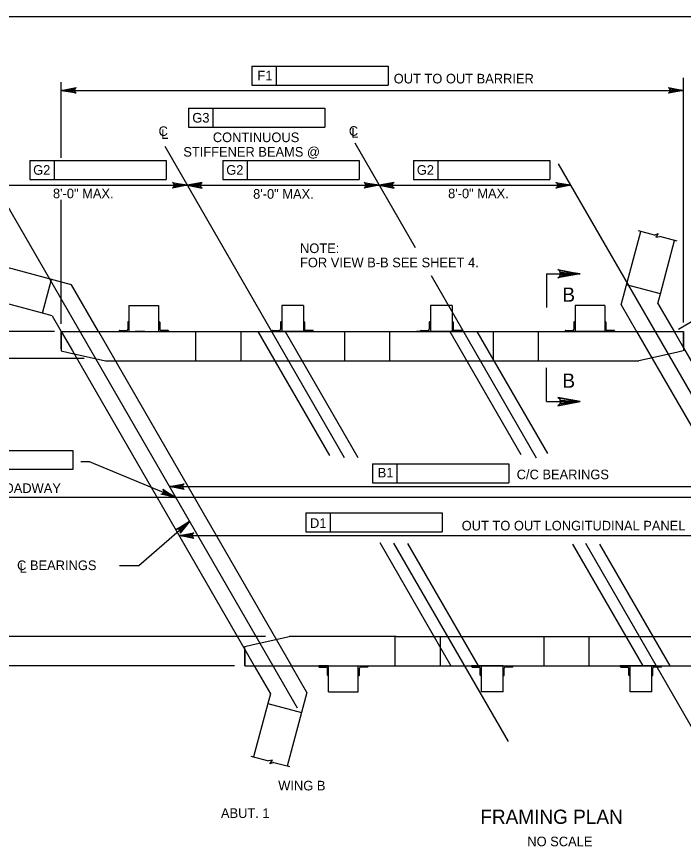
# Model space of a CAD drawing. Extents: x 638268 to 640277, y 295465 to 298435.
# Drawn here: x 639421 to 639628.9, y 296973.8 to 297232.5 of the extents above; entities that cross this region are included whole.
import ezdxf

# ---------------------------------------------------------------- set-up
doc = ezdxf.new("R2010")
doc.units = 0
for name, color, linetype in [('2', 7, 'Continuous'), ('3', 7, 'Continuous'), ('4', 7, 'Continuous')]:
    doc.layers.add(name, color=color, linetype=linetype)

msp = doc.modelspace()

# ---------------------------------------------------------------- linework, layer by layer
at = {"layer": '2'}
for p, q in [((639316.46, 297232.46), (640102.46, 297232.46)), ((639609.49, 297142.63), (639615.62, 297165.51)), ((639621.7, 297146.01), (639626.16, 297162.69)), ((639438.09, 297148.88), (639415.21, 297155.01)), ((639586.2, 297152.3), (639586.2, 297141.81)), ((639586.2, 297152.3), (639596.69, 297152.3)), ((639429.07, 297140), (639431.89, 297150.55)), ((639446.52, 297134.29), (639438.09, 297148.88)), ((639621.7, 297146.01), (639611.15, 297148.83)), ((639429.07, 297140), (639412.39, 297144.47)), ((639620.9, 297143.05), (639621.7, 297146.01)), ((639455.99, 297142.38), (639465.22, 297142.38)), ((639455.99, 297142.38), (639455.99, 297134.29)), ((639465.22, 297142.38), (639465.22, 297134.29)), ((639510.38, 297142.38), (639503.65, 297142.38)), ((639510.38, 297142.38), (639503.65, 297142.38)), ((639503.65, 297142.38), (639503.65, 297134.29)), ((639510.38, 297142.38), (639510.38, 297134.29)), ((639556.74, 297142.38), (639550.02, 297142.38)), ((639556.74, 297142.38), (639550.02, 297142.38)), ((639556.74, 297142.38), (639550.02, 297142.38)), ((639550.02, 297142.38), (639550.02, 297134.29)), ((639556.74, 297142.38), (639556.74, 297134.29)), ((639604.36, 297142.38), (639595.12, 297142.38)), ((639595.12, 297142.38), (639595.12, 297134.29)), ((639604.36, 297142.38), (639604.36, 297134.29)), ((639609.49, 297142.63), (639614.31, 297134.29)), ((639620.9, 297143.05), (639625.96, 297134.29)), ((639432.02, 297139.21), (639429.07, 297140)), ((639432.02, 297139.21), (639434.87, 297134.29)), ((639455.62, 297137.2), (639455.62, 297135.01)), ((639455.81, 297137.38), (639455.99, 297137.38)), ((639455.99, 297137.38), (639455.99, 297134.29)), ((639465.41, 297137.38), (639465.22, 297137.38)), ((639465.22, 297137.38), (639465.22, 297134.29)), ((639465.59, 297137.2), (639465.59, 297135.01)), ((639503.29, 297137.2), (639503.29, 297135.01)), ((639503.47, 297137.38), (639503.65, 297137.38)), ((639503.65, 297137.38), (639503.65, 297134.29)), ((639510.56, 297137.38), (639510.38, 297137.38)), ((639510.38, 297137.38), (639510.38, 297134.29)), ((639510.74, 297137.2), (639510.74, 297135.01)), ((639549.65, 297137.2), (639549.65, 297135.01)), ((639549.83, 297137.38), (639550.02, 297137.38)), ((639550.02, 297137.38), (639550.02, 297134.29)), ((639556.92, 297137.38), (639556.74, 297137.38)), ((639556.74, 297137.38), (639556.74, 297134.29)), ((639557.11, 297137.2), (639557.11, 297135.01)), ((639594.76, 297137.2), (639594.76, 297135.01)), ((639594.94, 297137.38), (639595.12, 297137.38)), ((639595.12, 297137.38), (639595.12, 297134.29)), ((639604.54, 297137.38), (639604.36, 297137.38)), ((639604.36, 297137.38), (639604.36, 297134.29)), ((639604.72, 297137.2), (639604.72, 297135.01)), ((639434.87, 297134.29), (639628.88, 297134.29)), ((639434.87, 297134.29), (639438.37, 297128.22)), ((639434.87, 297134.29), (639628.88, 297134.29)), ((639434.87, 297134.29), (639434.87, 297128.26)), ((639434.87, 297128.9), (639434.87, 297134.29)), ((639446.52, 297134.29), (639506.69, 297030.06)), ((639452.9, 297134.47), (639452.9, 297134.29)), ((639453.08, 297134.65), (639455.26, 297134.65)), ((639455.99, 297134.29), (639465.22, 297134.29)), ((639460.99, 297134.29), (639457.9, 297134.29)), ((639465.22, 297134.29), (639468.32, 297134.29)), ((639468.13, 297134.65), (639465.95, 297134.65)), ((639468.32, 297134.47), (639468.32, 297134.29)), ((639476.78, 297134.29), (639476.78, 297125.17)), ((639490.85, 297134.29), (639490.85, 297125.17)), ((639500.56, 297134.47), (639500.56, 297134.29)), ((639503.65, 297134.29), (639500.56, 297134.29)), ((639500.74, 297134.65), (639502.92, 297134.65)), ((639511.63, 297134.29), (639502.4, 297134.29)), ((639510.38, 297134.29), (639503.65, 297134.29)), ((639510.38, 297134.29), (639513.47, 297134.29)), ((639513.29, 297134.65), (639511.11, 297134.65)), ((639513.47, 297134.47), (639513.47, 297134.29)), ((639523.18, 297134.29), (639523.19, 297125.17)), ((639537.21, 297134.29), (639537.21, 297125.17)), ((639548.76, 297134.29), (639545.67, 297134.29)), ((639546.92, 297134.47), (639546.92, 297134.29)), ((639550.02, 297134.29), (639546.92, 297134.29)), ((639547.11, 297134.65), (639549.29, 297134.65)), ((639558, 297134.29), (639548.76, 297134.29)), ((639558, 297134.29), (639548.76, 297134.29)), ((639556.74, 297134.29), (639550.02, 297134.29)), ((639556.74, 297134.29), (639559.83, 297134.29)), ((639559.65, 297134.65), (639557.47, 297134.65)), ((639558, 297134.29), (639561.09, 297134.29)), ((639559.83, 297134.47), (639559.83, 297134.29)), ((639569.55, 297134.29), (639569.55, 297125.17)), ((639583.57, 297134.29), (639583.57, 297125.17)), ((639592.03, 297134.47), (639592.03, 297134.29)), ((639595.12, 297134.29), (639592.03, 297134.29)), ((639592.21, 297134.65), (639594.4, 297134.65)), ((639604.36, 297134.29), (639595.12, 297134.29)), ((639604.36, 297134.29), (639607.45, 297134.29)), ((639607.27, 297134.65), (639605.09, 297134.65)), ((639607.45, 297134.47), (639607.45, 297134.29)), ((639614.31, 297134.29), (639674.49, 297030.06)), ((639625.96, 297134.29), (639628.88, 297129.24)), ((639628.88, 297129.24), (639628.88, 297134.29)), ((639628.88, 297134.29), (639628.88, 297128.26)), ((639628.88, 297129.24), (639682.63, 297036.13)), ((639434.87, 297128.26), (639437.04, 297127.77)), ((639437.04, 297127.77), (639448.71, 297125.17)), ((639438.37, 297128.22), (639492.13, 297035.11)), ((639626.69, 297127.77), (639615.01, 297125.17)), ((639628.86, 297128.26), (639626.69, 297127.77)), ((639448.71, 297125.17), (639615.01, 297125.17)), ((639586.2, 297112.45), (639586.2, 297122.94)), ((639586.2, 297112.45), (639596.69, 297112.45)), ((639494.3, 297036.58), (639505.98, 297039.18)), ((639539.28, 297039.18), (639505.98, 297039.18)), ((639539.04, 297030.06), (639539.04, 297039.18)), ((639539.28, 297039.18), (639674.46, 297039.18)), ((639553.11, 297030.06), (639553.11, 297039.18)), ((639585.45, 297030.06), (639585.45, 297039.18)), ((639599.47, 297030.06), (639599.47, 297039.18)), ((639492.13, 297036.09), (639494.3, 297036.58)), ((639492.13, 297030.06), (639492.13, 297036.09)), ((639492.13, 297035.23), (639492.13, 297030.06)), ((639492.13, 297035.11), (639495.04, 297030.06)), ((639492.13, 297030.06), (639686.14, 297030.06)), ((639492.13, 297030.06), (639686.14, 297030.06)), ((639495.04, 297030.06), (639500.1, 297021.3)), ((639511.51, 297021.72), (639506.69, 297030.06)), ((639515.16, 297029.88), (639515.16, 297030.06)), ((639518.25, 297030.06), (639515.16, 297030.06)), ((639515.34, 297029.7), (639517.52, 297029.7)), ((639517.88, 297027.15), (639517.88, 297029.33)), ((639518.25, 297030.06), (639527.49, 297030.06)), ((639518.25, 297026.97), (639518.25, 297030.06)), ((639518.25, 297021.97), (639518.25, 297030.06)), ((639527.49, 297030.06), (639530.58, 297030.06)), ((639527.49, 297026.97), (639527.49, 297030.06)), ((639527.49, 297021.97), (639527.49, 297030.06)), ((639527.85, 297027.15), (639527.85, 297029.33)), ((639530.39, 297029.7), (639528.21, 297029.7)), ((639530.58, 297029.88), (639530.58, 297030.06)), ((639562.82, 297029.88), (639562.82, 297030.06)), ((639565.91, 297030.06), (639562.82, 297030.06)), ((639563, 297029.7), (639565.18, 297029.7)), ((639565.55, 297027.15), (639565.55, 297029.33)), ((639572.64, 297030.06), (639565.91, 297030.06)), ((639565.91, 297026.97), (639565.91, 297030.06)), ((639565.91, 297021.97), (639565.91, 297030.06)), ((639572.64, 297026.97), (639572.64, 297030.06)), ((639572.64, 297030.06), (639575.73, 297030.06)), ((639572.64, 297021.97), (639572.64, 297030.06)), ((639573, 297027.15), (639573, 297029.33)), ((639575.55, 297029.7), (639573.37, 297029.7)), ((639575.73, 297029.88), (639575.73, 297030.06)), ((639609.18, 297029.88), (639609.18, 297030.06)), ((639612.28, 297030.06), (639609.18, 297030.06)), ((639609.37, 297029.7), (639611.55, 297029.7)), ((639620.26, 297030.06), (639611.02, 297030.06)), ((639611.91, 297027.15), (639611.91, 297029.33)), ((639619, 297030.06), (639612.28, 297030.06)), ((639612.28, 297026.97), (639612.28, 297030.06)), ((639612.28, 297021.97), (639612.28, 297030.06)), ((639619, 297026.97), (639619, 297030.06)), ((639619, 297030.06), (639622.09, 297030.06)), ((639619, 297021.97), (639619, 297030.06)), ((639619.37, 297027.15), (639619.37, 297029.33)), ((639621.91, 297029.7), (639619.73, 297029.7)), ((639622.09, 297029.88), (639622.09, 297030.06)), ((639518.07, 297026.97), (639518.25, 297026.97)), ((639527.67, 297026.97), (639527.49, 297026.97)), ((639565.73, 297026.97), (639565.91, 297026.97)), ((639572.82, 297026.97), (639572.64, 297026.97)), ((639612.09, 297026.97), (639612.28, 297026.97)), ((639619.18, 297026.97), (639619, 297026.97)), ((639500.1, 297021.3), (639499.31, 297018.34)), ((639511.51, 297021.72), (639505.38, 296998.84)), ((639518.25, 297021.97), (639527.49, 297021.97)), ((639572.64, 297021.97), (639565.91, 297021.97)), ((639619, 297021.97), (639612.28, 297021.97)), ((639619, 297021.97), (639612.28, 297021.97)), ((639499.31, 297018.34), (639494.84, 297001.66)), ((639499.31, 297018.34), (639509.85, 297015.52))]:
    msp.add_line(p, q, dxfattribs=at)
for points in [[(639596.69, 297152.3), (639589.7, 297150.99), (639590.24, 297151.36), (639590.51, 297151.83), (639590.59, 297152.3), (639590.51, 297152.77), (639590.24, 297153.24), (639589.7, 297153.61), (639596.69, 297152.3), (639590.24, 297153.24), (639590.51, 297152.77), (639596.69, 297152.3), (639590.59, 297152.3), (639590.51, 297151.83), (639596.69, 297152.3), (639590.24, 297151.36)], [(639596.69, 297112.45), (639589.7, 297113.76), (639590.24, 297113.39), (639590.51, 297112.92), (639590.59, 297112.45), (639590.51, 297111.99), (639590.24, 297111.52), (639589.7, 297111.15), (639596.69, 297112.45), (639590.24, 297111.52), (639590.51, 297111.99), (639596.69, 297112.45), (639590.59, 297112.45), (639590.51, 297112.92), (639596.69, 297112.45), (639590.24, 297113.39)]]:
    msp.add_lwpolyline(points, dxfattribs=at)
for centre, radius, start, end in [((639455.81, 297137.2), 0.182, 90, 179.9984), ((639465.41, 297137.2), 0.182, 0.0016, 90), ((639503.47, 297137.2), 0.182, 90, 179.9984), ((639510.56, 297137.2), 0.182, 0.0016, 90), ((639549.83, 297137.2), 0.182, 90, 179.9984), ((639556.92, 297137.2), 0.182, 0.0016, 90), ((639594.94, 297137.2), 0.182, 90, 179.9984), ((639604.54, 297137.2), 0.182, 0.0016, 90), ((639453.08, 297134.47), 0.182, 90, 179.9984), ((639455.26, 297135.01), 0.364, 270, 359.9984), ((639465.95, 297135.01), 0.364, 180.0016, 270), ((639468.13, 297134.47), 0.182, 0.0016, 90), ((639500.74, 297134.47), 0.182, 90, 179.9984), ((639502.92, 297135.01), 0.364, 270, 359.9984), ((639511.11, 297135.01), 0.364, 180.0016, 270), ((639513.29, 297134.47), 0.182, 0.0016, 90), ((639547.11, 297134.47), 0.182, 90, 179.9984), ((639549.29, 297135.01), 0.364, 270, 359.9984), ((639557.47, 297135.01), 0.364, 180.0016, 270), ((639559.65, 297134.47), 0.182, 0.0016, 90), ((639592.21, 297134.47), 0.182, 90, 179.9984), ((639594.4, 297135.01), 0.364, 270, 359.9984), ((639605.09, 297135.01), 0.364, 180.0016, 270), ((639607.27, 297134.47), 0.182, 0.0016, 90), ((639515.34, 297029.88), 0.182, 180.0016, 270), ((639517.52, 297029.33), 0.364, 0.0016, 90), ((639528.21, 297029.33), 0.364, 90, 179.9984), ((639530.39, 297029.88), 0.182, 270, 359.9984), ((639563, 297029.88), 0.182, 180.0016, 270), ((639565.18, 297029.33), 0.364, 0.0016, 90), ((639573.37, 297029.33), 0.364, 90, 179.9984), ((639575.55, 297029.88), 0.182, 270, 359.9984), ((639609.37, 297029.88), 0.182, 180.0016, 270), ((639611.55, 297029.33), 0.364, 0.0016, 90), ((639619.73, 297029.33), 0.364, 90, 179.9984), ((639621.91, 297029.88), 0.182, 270, 359.9984), ((639518.07, 297027.15), 0.182, 180.0016, 270), ((639527.67, 297027.15), 0.182, 270, 359.9984), ((639565.73, 297027.15), 0.182, 180.0016, 270), ((639572.82, 297027.15), 0.182, 270, 359.9984), ((639612.09, 297027.15), 0.182, 180.0016, 270), ((639619.18, 297027.15), 0.182, 270, 359.9984)]:
    msp.add_arc(centre, radius, start, end, dxfattribs=at)
at = {"layer": '3'}
for p, q in [((639619.88, 297164.37), (639614.88, 297165.71)), ((639619.88, 297164.37), (639621.06, 297164.87)), ((639621.06, 297164.87), (639620.25, 297163.65)), ((639620.25, 297163.65), (639621.51, 297163.93)), ((639626.98, 297162.47), (639621.51, 297163.93)), ((639496.22, 297134.29), (639518.55, 297095.6)), ((639504.68, 297134.29), (639527.35, 297095.02)), ((639556.04, 297134.29), (639578.16, 297095.97)), ((639564.5, 297134.29), (639586.47, 297096.22)), ((639534.21, 297068.49), (639556.4, 297030.06)), ((639542.81, 297068.24), (639564.86, 297030.06)), ((639594.32, 297067.98), (639616.21, 297030.06)), ((639602.77, 297067.99), (639624.67, 297030.06)), ((639494.02, 297001.88), (639499.5, 297000.42)), ((639500.75, 297000.7), (639499.5, 297000.42)), ((639499.95, 296999.47), (639500.75, 297000.7)), ((639501.12, 296999.98), (639499.95, 296999.47)), ((639501.12, 296999.98), (639506.13, 296998.64))]:
    msp.add_line(p, q, dxfattribs=at)
at = {"layer": '4'}
for p, q in [((639494.33, 297217.02), (639536.85, 297217.02)), ((639494.33, 297217.02), (639494.33, 297211.12)), ((639501.89, 297217.02), (639501.89, 297211.12)), ((639536.85, 297217.02), (639536.85, 297211.12)), ((639434.87, 297188.47), (639434.87, 297211.99)), ((639628.88, 297137.07), (639628.88, 297213.37)), ((639434.87, 297209.44), (639628.88, 297209.44)), ((639494.33, 297211.12), (639536.85, 297211.12)), ((639474.59, 297203.87), (639517.11, 297203.87)), ((639474.59, 297203.87), (639474.59, 297197.97)), ((639482.15, 297203.87), (639482.15, 297197.97)), ((639517.11, 297203.87), (639517.11, 297197.97)), ((639474.59, 297197.97), (639517.11, 297197.97)), ((639467.19, 297192.03), (639523.11, 297095.04)), ((639526.39, 297193.1), (639545.21, 297160.45)), ((639425.09, 297187.61), (639467.61, 297187.61)), ((639425.09, 297187.61), (639425.09, 297181.7)), ((639432.65, 297187.61), (639432.65, 297181.7)), ((639467.61, 297187.61), (639467.61, 297181.7)), ((639485.29, 297187.61), (639527.81, 297187.61)), ((639485.29, 297187.61), (639485.29, 297181.7)), ((639492.85, 297187.61), (639492.85, 297181.7)), ((639527.81, 297187.61), (639527.81, 297181.7)), ((639544.73, 297187.61), (639587.25, 297187.61)), ((639544.73, 297187.61), (639544.73, 297181.7)), ((639552.29, 297187.61), (639552.29, 297181.7)), ((639587.25, 297187.61), (639587.25, 297181.7)), ((639688.63, 297015.66), (639589.95, 297186.58)), ((639508.5, 297016.85), (639411.4, 297185.03)), ((639425.09, 297181.7), (639467.61, 297181.7)), ((639485.29, 297181.7), (639527.81, 297181.7)), ((639544.73, 297181.7), (639587.25, 297181.7)), ((639627.32, 297135.07), (639707.53, 297181.38)), ((639414.36, 297179.9), (639593.8, 297179.9)), ((639434.87, 297136.69), (639434.87, 297175.34)), ((639550.24, 297151.72), (639583.01, 297094.89)), ((639432.73, 297134.29), (639336.8, 297134.29)), ((639442, 297125.83), (639376.05, 297125.83)), ((639395.98, 297097.16), (639438.5, 297097.16)), ((639438.5, 297097.16), (639438.5, 297091.26)), ((639443.71, 297093.63), (639440.95, 297093.63)), ((639443.78, 297093.63), (639440.95, 297093.63)), ((639470.55, 297082.58), (639443.71, 297093.63)), ((639531.94, 297093.01), (639574.46, 297093.01)), ((639531.94, 297093.01), (639531.94, 297087.11)), ((639539.5, 297093.01), (639539.5, 297087.11)), ((639574.46, 297093.01), (639574.46, 297087.11)), ((639438.5, 297091.26), (639395.98, 297091.26)), ((639468.6, 297085.95), (639648.04, 297085.95)), ((639531.94, 297087.11), (639574.46, 297087.11)), ((639707.69, 297082.58), (639405.47, 297082.58)), ((639511.19, 297077.75), (639553.71, 297077.75)), ((639511.19, 297077.75), (639511.19, 297071.85)), ((639518.75, 297077.75), (639518.75, 297071.85)), ((639553.71, 297077.75), (639553.71, 297071.85)), ((639459.03, 297061.32), (639474.87, 297075.1)), ((639511.19, 297071.85), (639553.71, 297071.85)), ((639471.61, 297070.65), (639662.7, 297070.65)), ((639538.53, 297068.34), (639574.21, 297006.52)), ((639598.34, 297068.34), (639634.03, 297006.52)), ((639453.05, 297061.32), (639459.03, 297061.32)), ((639498.57, 297039.18), (639376.05, 297039.18)), ((639488.89, 297030.06), (639336.8, 297030.06))]:
    msp.add_line(p, q, dxfattribs=at)
for points in [[(639434.87, 297209.44), (639439.53, 297210.31), (639439.17, 297210.06), (639438.98, 297209.75), (639438.93, 297209.44), (639438.98, 297209.13), (639439.17, 297208.81), (639439.53, 297208.57), (639434.87, 297209.44), (639439.17, 297208.81), (639438.98, 297209.13), (639434.87, 297209.44), (639438.93, 297209.44), (639438.98, 297209.75), (639434.87, 297209.44), (639439.17, 297210.06)], [(639628.88, 297209.44), (639624.22, 297208.57), (639624.58, 297208.81), (639624.76, 297209.13), (639624.82, 297209.44), (639624.76, 297209.75), (639624.58, 297210.06), (639624.22, 297210.31), (639628.88, 297209.44), (639624.58, 297210.06), (639624.76, 297209.75), (639628.88, 297209.44), (639624.82, 297209.44), (639624.76, 297209.13), (639628.88, 297209.44), (639624.58, 297208.81)], [(639474.19, 297179.9), (639469.53, 297179.02), (639469.88, 297179.27), (639470.07, 297179.59), (639470.12, 297179.9), (639470.07, 297180.21), (639469.88, 297180.52), (639469.53, 297180.77), (639474.19, 297179.9), (639469.88, 297180.52), (639470.07, 297180.21), (639474.19, 297179.9), (639470.12, 297179.9), (639470.07, 297179.59), (639474.19, 297179.9), (639469.88, 297179.27)], [(639474.19, 297179.9), (639478.85, 297179.02), (639478.49, 297179.27), (639478.3, 297179.59), (639478.25, 297179.9), (639478.3, 297180.21), (639478.49, 297180.52), (639478.85, 297180.77), (639474.19, 297179.9), (639478.49, 297180.52), (639478.3, 297180.21), (639474.19, 297179.9), (639478.25, 297179.9), (639478.3, 297179.59), (639474.19, 297179.9), (639478.49, 297179.27)], [(639534, 297179.9), (639529.34, 297179.02), (639529.7, 297179.27), (639529.88, 297179.59), (639529.94, 297179.9), (639529.88, 297180.21), (639529.7, 297180.52), (639529.34, 297180.77), (639534, 297179.9), (639529.7, 297180.52), (639529.88, 297180.21), (639534, 297179.9), (639529.94, 297179.9), (639529.88, 297179.59), (639534, 297179.9), (639529.7, 297179.27)], [(639534, 297179.9), (639538.66, 297179.02), (639538.3, 297179.27), (639538.12, 297179.59), (639538.06, 297179.9), (639538.12, 297180.21), (639538.3, 297180.52), (639538.66, 297180.77), (639534, 297179.9), (639538.3, 297180.52), (639538.12, 297180.21), (639534, 297179.9), (639538.06, 297179.9), (639538.12, 297179.59), (639534, 297179.9), (639538.3, 297179.27)], [(639593.8, 297179.9), (639589.14, 297179.02), (639589.5, 297179.27), (639589.69, 297179.59), (639589.74, 297179.9), (639589.69, 297180.21), (639589.5, 297180.52), (639589.14, 297180.77), (639593.8, 297179.9), (639589.5, 297180.52), (639589.69, 297180.21), (639593.8, 297179.9), (639589.74, 297179.9), (639589.69, 297179.59), (639593.8, 297179.9), (639589.5, 297179.27)], [(639470.55, 297082.58), (639465.91, 297083.55), (639466.33, 297083.64), (639466.62, 297083.86), (639466.79, 297084.13), (639466.86, 297084.44), (639466.81, 297084.8), (639466.57, 297085.16), (639470.55, 297082.58), (639466.81, 297084.8), (639466.86, 297084.44), (639470.55, 297082.58), (639466.79, 297084.13), (639466.62, 297083.86), (639470.55, 297082.58), (639466.33, 297083.64)], [(639468.6, 297085.95), (639473.26, 297086.83), (639472.9, 297086.58), (639472.72, 297086.27), (639472.66, 297085.95), (639472.72, 297085.64), (639472.9, 297085.33), (639473.26, 297085.08), (639468.6, 297085.95), (639472.9, 297085.33), (639472.72, 297085.64), (639468.6, 297085.95), (639472.66, 297085.95), (639472.72, 297086.27), (639468.6, 297085.95), (639472.9, 297086.58)], [(639474.87, 297075.1), (639471.92, 297071.38), (639472.03, 297071.8), (639471.97, 297072.16), (639471.8, 297072.43), (639471.56, 297072.63), (639471.21, 297072.75), (639470.78, 297072.7), (639474.87, 297075.1), (639471.21, 297072.75), (639471.56, 297072.63), (639474.87, 297075.1), (639471.8, 297072.43), (639471.97, 297072.16), (639474.87, 297075.1), (639472.03, 297071.8)], [(639471.61, 297070.65), (639476.27, 297071.52), (639475.91, 297071.28), (639475.72, 297070.96), (639475.67, 297070.65), (639475.72, 297070.34), (639475.91, 297070.03), (639476.27, 297069.78), (639471.61, 297070.65), (639475.91, 297070.03), (639475.72, 297070.34), (639471.61, 297070.65), (639475.67, 297070.65), (639475.72, 297070.96), (639471.61, 297070.65), (639475.91, 297071.28)]]:
    msp.add_lwpolyline(points, dxfattribs=at)
msp.add_lwpolyline([(639467.81, 297083.21), (639468.16, 297084.06), (639470.55, 297082.58)], close=True, dxfattribs=at)

# ---------------------------------------------------------------- texts
for s, height, rotation, p in [('F1', 3, 359.9382, (639496.05, 297212.57)), ('G3', 3, 359.9382, (639475.75, 297199.42)), ('G2', 3, 359.9382, (639426.12, 297183.15)), ('G2', 3, 359.9382, (639486.33, 297183.15)), ('G2', 3, 359.9382, (639545.76, 297183.15)), ('8\'-0" MAX.', 3, 359.9382, (639432.29, 297175.83)), ('8\'-0" MAX.', 3, 359.9382, (639494.71, 297175.68)), ('8\'-0" MAX.', 3, 359.9382, (639555.51, 297175.83)), ('B', 4.43, 360, (639591.15, 297143.57)), ('B', 4.43, 360, (639591.15, 297116.75)), ('B1', 3, 359.9382, (639533.56, 297088.79)), ('D1', 3, 359.9382, (639512.45, 297073.07))]:
    msp.add_text(s, height=height, rotation=rotation, dxfattribs=at).set_placement(p)
for s, height, p in [('OUT TO OUT BARRIER ', 3, (639538.56, 297211.62)), ('C', 3, (639465.22, 297195.24)), ('L', 3, (639466.05, 297194.35)), ('CONTINUOUS', 3, (639482.15, 297193.32)), ('C', 3, (639524.56, 297195.29)), ('L', 3, (639525.35, 297194.71)), ('STIFFENER BEAMS @', 3, (639472.94, 297188.8)), ('NOTE:', 3, (639509.34, 297158.74)), ('FOR VIEW B-B SEE SHEET 4.', 3, (639509.34, 297154.3)), ('C/C BEARINGS', 3, (639576.91, 297088.23)), ('L ROADWAY', 3, (639410.7, 297083.96)), ('OUT TO OUT LONGITUDINAL PANEL', 3, (639559.76, 297072.27)), ('C BEARINGS', 3, (639421.11, 297059.91)), ('L', 3, (639421.85, 297059.13)), ('WING B', 3, (639502.55, 296991.23)), ('ABUT. 1', 3, (639484.69, 296982.64)), ('FRAMING PLAN', 4.4292, (639565.55, 296980.81)), ('NO SCALE', 3, (639580.22, 296973.82))]:
    msp.add_text(s, height=height, dxfattribs=at).set_placement(p)

doc.saveas('drawing.dxf')
